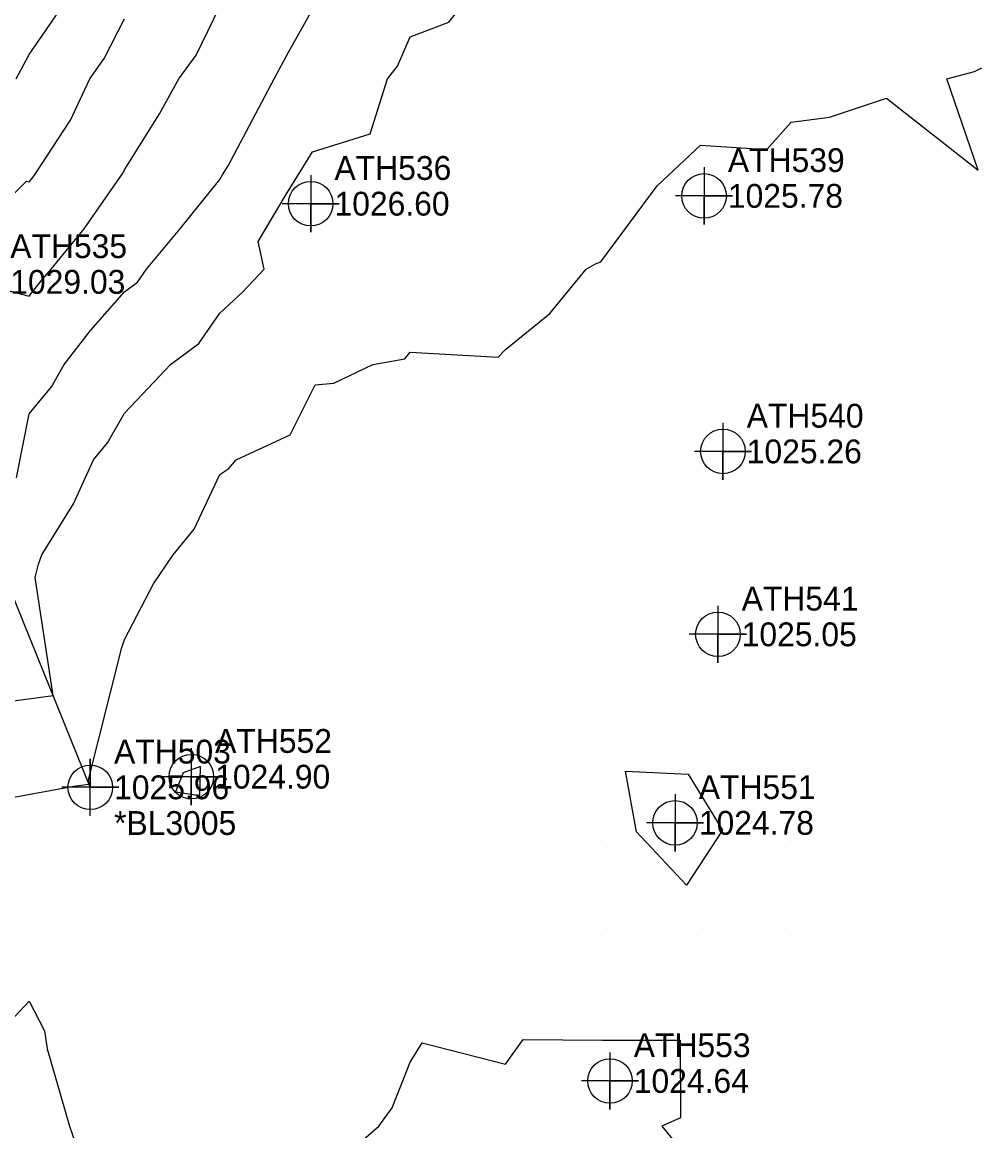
# Model space of a CAD drawing. Extents: x 1213164 to 1213550, y 766120 to 766870.
# Drawn here: x 1213419.3 to 1213520, y 766539.5 to 766656 of the extents above; entities that cross this region are included whole.
import ezdxf

# ---------------------------------------------------------------- set-up
doc = ezdxf.new("R2010")
doc.units = 0
for name, color, linetype in [('Default', 7, 'Continuous'), ('Exist DTM QL2 LIDAR Elevation Point', 7, 'Continuous'), ('Exist DTM Regular Point CELL', 7, 'Continuous'), ('Exist DTM Regular Point Cogo Elevation', 7, 'Continuous'), ('Exist DTM Regular Point Cogo Number', 7, 'Continuous'), ('Exist Roads Soil', 7, 'Continuous'), ('Exist Roads Soil Cogo Comment', 7, 'Continuous'), ('Exist Roads Soil Cogo Elevation', 7, 'Continuous'), ('Exist Roads Soil Cogo Number', 7, 'Continuous'), ('Exist Roads Soil Cogo Point CELL', 7, 'Continuous')]:
    doc.layers.add(name, color=color, linetype=linetype)

msp = doc.modelspace()

# ---------------------------------------------------------------- linework, layer by layer
at = {"layer": 'Default'}
for points in [[(1213403.52, 766582.69), (1213422.5, 766585.23), (1213420.62, 766597.62), (1213420.98, 766599.02), (1213421.33, 766600), (1213424.63, 766605.37), (1213426.75, 766610), (1213428.22, 766611.78), (1213430, 766614.9), (1213432.49, 766617.51), (1213434.81, 766620), (1213437.8, 766622.2), (1213440, 766625.38), (1213442.39, 766627.61), (1213444.66, 766630), (1213444.04, 766632.92), (1213446.89, 766637.76), (1213449.73, 766642.35), (1213455.77, 766644.23), (1213457.62, 766650), (1213458.66, 766651.34), (1213460, 766654.4), (1213464.06, 766655.94), (1213467.28, 766660)], [(1213415.71, 766628.28), (1213420, 766627.19), (1213421.23, 766628.77), (1213422.3, 766630), (1213425.75, 766634.25), (1213429.76, 766640), (1213429.86, 766640.14), (1213430, 766640.45), (1213433.66, 766646.34), (1213435.71, 766650), (1213437.52, 766652.48), (1213440, 766657.61)], [(1213418.63, 766650), (1213420, 766652.57), (1213423.02, 766656.98)], [(1213418.64, 766608.1), (1213420, 766614.82), (1213422.34, 766617.66), (1213423.67, 766620), (1213426.43, 766623.57), (1213430, 766627.64), (1213431.36, 766628.64), (1213432.3, 766630), (1213435.8, 766634.2), (1213440, 766639.44), (1213440.28, 766639.91), (1213440.87, 766640.87), (1213445.71, 766650), (1213447.2, 766652.8), (1213450, 766657.79)], [(1213353.03, 766538.71), (1213360.06, 766554.63), (1213361.94, 766557.96), (1213368.09, 766570.88), (1213369.21, 766573.11), (1213376.08, 766587.44), (1213384.56, 766603.77), (1213386.66, 766605.05), (1213387.56, 766605.71), (1213391.04, 766602.72), (1213405.84, 766608.43), (1213411.21, 766613.12), (1213411.8, 766620.77), (1213412.59, 766627.41), (1213412.01, 766629.52), (1213413.41, 766632.98), (1213419.7, 766639.25), (1213420, 766639.17), (1213420.37, 766639.63), (1213420.63, 766640), (1213424.33, 766645.67), (1213426.37, 766650), (1213427.85, 766652.15), (1213430, 766656.29)], [(1213406.87, 766572.47), (1213424.68, 766575.72), (1213426.26, 766575.93), (1213426.2, 766576.36), (1213429.71, 766590.29), (1213430, 766591.12), (1213433.03, 766596.97), (1213435.12, 766600), (1213437.31, 766602.69), (1213440, 766608.43), (1213440.94, 766609.06), (1213441.71, 766610), (1213447.4, 766612.6), (1213450, 766617.85), (1213451.97, 766618.03), (1213456.08, 766620), (1213459.42, 766620.58), (1213460, 766621.3), (1213469.24, 766620.76), (1213470, 766621.58), (1213474.66, 766625.34), (1213478.46, 766630), (1213479.44, 766630.56), (1213480, 766630.78), (1213485.92, 766638.75), (1213490.48, 766643.05), (1213497.43, 766642.57), (1213500, 766645.44), (1213504.02, 766645.98), (1213510, 766647.97), (1213519.6, 766640.4), (1213516.31, 766650), (1213519.24, 766650.76), (1213520, 766651.16)], [(1213437.98, 766577.78), (1213436.14, 766577.12), (1213435.34, 766575.12), (1213437.89, 766574.74), (1213437.98, 766577.78)], [(1213482.59, 766577.3), (1213489.18, 766576.97), (1213492.77, 766571.1), (1213489.01, 766565.31), (1213483.75, 766570.9), (1213482.59, 766577.3)], [(1213403.65, 766536.35), (1213401.85, 766540), (1213405.16, 766544.84), (1213405.95, 766550), (1213407.62, 766552.38), (1213410, 766555.03), (1213418.49, 766551.51), (1213420, 766553.14), (1213421.59, 766550), (1213421.87, 766548.13), (1213424.23, 766540), (1213426.51, 766533.49)], [(1213453.12, 766536.88), (1213456.69, 766540), (1213458.08, 766541.92), (1213460, 766546.73), (1213461.24, 766548.76), (1213470, 766546.5), (1213471.84, 766549.12), (1213480.17, 766549.05), (1213488.33, 766549.03), (1213488.36, 766540.86), (1213486.39, 766540), (1213490, 766535.63)]]:
    msp.add_lwpolyline(points, dxfattribs=at)
at = {"layer": 'Exist DTM QL2 LIDAR Elevation Point'}
for p, q in [((1213420, 766650), (1213420, 766650)), ((1213430, 766650), (1213430, 766650)), ((1213440, 766650), (1213440, 766650)), ((1213450, 766650), (1213450, 766650)), ((1213460, 766650), (1213460, 766650)), ((1213470, 766650), (1213470, 766650)), ((1213480, 766650), (1213480, 766650)), ((1213490, 766650), (1213490, 766650)), ((1213500, 766650), (1213500, 766650)), ((1213510, 766650), (1213510, 766650)), ((1213520, 766650), (1213520, 766650)), ((1213420, 766640), (1213420, 766640)), ((1213430, 766640), (1213430, 766640)), ((1213440, 766640), (1213440, 766640)), ((1213460, 766640), (1213460, 766640)), ((1213470, 766640), (1213470, 766640)), ((1213480, 766640), (1213480, 766640)), ((1213500, 766640), (1213500, 766640)), ((1213510, 766640), (1213510, 766640)), ((1213520, 766640), (1213520, 766640)), ((1213420, 766630), (1213420, 766630)), ((1213430, 766630), (1213430, 766630)), ((1213440, 766630), (1213440, 766630)), ((1213450, 766630), (1213450, 766630)), ((1213460, 766630), (1213460, 766630)), ((1213470, 766630), (1213470, 766630)), ((1213480, 766630), (1213480, 766630)), ((1213490, 766630), (1213490, 766630)), ((1213500, 766630), (1213500, 766630)), ((1213510, 766630), (1213510, 766630)), ((1213420, 766620), (1213420, 766620)), ((1213430, 766620), (1213430, 766620)), ((1213440, 766620), (1213440, 766620)), ((1213450, 766620), (1213450, 766620)), ((1213460, 766620), (1213460, 766620)), ((1213470, 766620), (1213470, 766620)), ((1213480, 766620), (1213480, 766620)), ((1213490, 766620), (1213490, 766620)), ((1213500, 766620), (1213500, 766620)), ((1213510, 766620), (1213510, 766620)), ((1213420, 766610), (1213420, 766610)), ((1213430, 766610), (1213430, 766610)), ((1213440, 766610), (1213440, 766610)), ((1213450, 766610), (1213450, 766610)), ((1213460, 766610), (1213460, 766610)), ((1213470, 766610), (1213470, 766610)), ((1213480, 766610), (1213480, 766610)), ((1213500, 766610), (1213500, 766610)), ((1213510, 766610), (1213510, 766610)), ((1213420, 766600), (1213420, 766600)), ((1213430, 766600), (1213430, 766600)), ((1213440, 766600), (1213440, 766600)), ((1213450, 766600), (1213450, 766600)), ((1213460, 766600), (1213460, 766600)), ((1213470, 766600), (1213470, 766600)), ((1213480, 766600), (1213480, 766600)), ((1213490, 766600), (1213490, 766600)), ((1213500, 766600), (1213500, 766600)), ((1213510, 766600), (1213510, 766600)), ((1213430, 766590), (1213430, 766590)), ((1213440, 766590), (1213440, 766590)), ((1213450, 766590), (1213450, 766590)), ((1213460, 766590), (1213460, 766590)), ((1213470, 766590), (1213470, 766590)), ((1213480, 766590), (1213480, 766590)), ((1213500, 766590), (1213500, 766590)), ((1213510, 766590), (1213510, 766590)), ((1213430, 766580), (1213430, 766580)), ((1213440, 766580), (1213440, 766580)), ((1213450, 766580), (1213450, 766580)), ((1213460, 766580), (1213460, 766580)), ((1213470, 766580), (1213470, 766580)), ((1213480, 766580), (1213480, 766580)), ((1213490, 766580), (1213490, 766580)), ((1213500, 766580), (1213500, 766580)), ((1213510, 766580), (1213510, 766580)), ((1213420, 766570), (1213420, 766570)), ((1213430, 766570), (1213430, 766570)), ((1213440, 766570), (1213440, 766570)), ((1213450, 766570), (1213450, 766570)), ((1213460, 766570), (1213460, 766570)), ((1213470, 766570), (1213470, 766570)), ((1213480, 766570), (1213480, 766570)), ((1213500, 766570), (1213500, 766570)), ((1213420, 766560), (1213420, 766560)), ((1213430, 766560), (1213430, 766560)), ((1213440, 766560), (1213440, 766560)), ((1213450, 766560), (1213450, 766560)), ((1213460, 766560), (1213460, 766560)), ((1213470, 766560), (1213470, 766560)), ((1213480, 766560), (1213480, 766560)), ((1213490, 766560), (1213490, 766560)), ((1213500, 766560), (1213500, 766560)), ((1213420, 766550), (1213420, 766550)), ((1213430, 766550), (1213430, 766550)), ((1213440, 766550), (1213440, 766550)), ((1213450, 766550), (1213450, 766550)), ((1213460, 766550), (1213460, 766550)), ((1213470, 766550), (1213470, 766550)), ((1213480, 766550), (1213480, 766550)), ((1213490, 766550), (1213490, 766550)), ((1213500, 766550), (1213500, 766550)), ((1213420, 766540), (1213420, 766540)), ((1213430, 766540), (1213430, 766540)), ((1213440, 766540), (1213440, 766540)), ((1213450, 766540), (1213450, 766540)), ((1213460, 766540), (1213460, 766540)), ((1213470, 766540), (1213470, 766540)), ((1213480, 766540), (1213480, 766540)), ((1213490, 766540), (1213490, 766540)), ((1213500, 766540), (1213500, 766540))]:
    msp.add_line(p, q, dxfattribs=at)
at = {"layer": 'Exist DTM Regular Point CELL'}
for points in [[(1213490.84, 766640.71), (1213490.84, 766634.71), (1213490.84, 766637.71), (1213493.84, 766637.71), (1213487.84, 766637.71)], [(1213449.54, 766639.89), (1213449.54, 766633.89), (1213449.54, 766636.89), (1213452.54, 766636.89), (1213446.54, 766636.89)], [(1213492.82, 766613.87), (1213492.82, 766607.87), (1213492.82, 766610.87), (1213495.82, 766610.87), (1213489.82, 766610.87)], [(1213492.29, 766594.66), (1213492.29, 766588.66), (1213492.29, 766591.66), (1213495.29, 766591.66), (1213489.29, 766591.66)], [(1213437.01, 766579.71), (1213437.01, 766573.71), (1213437.01, 766576.71), (1213440.01, 766576.71), (1213434.01, 766576.71)], [(1213487.79, 766574.86), (1213487.79, 766568.86), (1213487.79, 766571.86), (1213490.79, 766571.86), (1213484.79, 766571.86)], [(1213480.96, 766547.75), (1213480.96, 766541.75), (1213480.96, 766544.75), (1213483.96, 766544.75), (1213477.96, 766544.75)]]:
    msp.add_lwpolyline(points, dxfattribs=at)
for centre in [(1213449.54, 766636.89), (1213490.84, 766637.71), (1213492.82, 766610.87), (1213492.29, 766591.66), (1213437.01, 766576.71), (1213487.79, 766571.86), (1213480.96, 766544.75)]:
    msp.add_circle(centre, 2.34, dxfattribs=at)
at = {"layer": 'Exist Roads Soil'}
msp.add_line((1213426.4, 766575.59), (1213398.12, 766645.45), dxfattribs=at)
at = {"layer": 'Exist Roads Soil Cogo Point CELL'}
msp.add_lwpolyline([(1213426.4, 766572.59), (1213426.4, 766578.59), (1213426.4, 766575.59), (1213429.4, 766575.59), (1213423.4, 766575.59)], dxfattribs=at)
msp.add_circle((1213426.4, 766575.59), 2.34, dxfattribs=at)

# ---------------------------------------------------------------- texts
at = {"layer": 'Exist DTM Regular Point Cogo Elevation'}
for s, p in [('1026.60', (1213452.04, 766635.64)), ('1025.78', (1213493.34, 766636.46)), ('1029.03', (1213418, 766627.43)), ('1025.26', (1213495.32, 766609.62)), ('1025.05', (1213494.79, 766590.41)), ('1024.90', (1213439.51, 766575.46)), ('1024.78', (1213490.29, 766570.61)), ('1024.64', (1213483.46, 766543.5))]:
    msp.add_text(s, height=2.5, dxfattribs=at).set_placement(p)
at = {"layer": 'Exist DTM Regular Point Cogo Number'}
for s, p in [('ATH539', (1213493.34, 766640.21)), ('ATH536', (1213452.04, 766639.39)), ('ATH535', (1213418, 766631.18)), ('ATH540', (1213495.32, 766613.37)), ('ATH541', (1213494.79, 766594.16)), ('ATH552', (1213439.51, 766579.21)), ('ATH551', (1213490.29, 766574.36)), ('ATH553', (1213483.46, 766547.25))]:
    msp.add_text(s, height=2.5, dxfattribs=at).set_placement(p)
at = {"layer": 'Exist Roads Soil Cogo Comment'}
msp.add_text('*BL3005', height=2.5, dxfattribs=at).set_placement((1213428.9, 766570.59))
at = {"layer": 'Exist Roads Soil Cogo Elevation'}
msp.add_text('1025.96', height=2.5, dxfattribs=at).set_placement((1213428.9, 766574.34))
at = {"layer": 'Exist Roads Soil Cogo Number'}
msp.add_text('ATH503', height=2.5, dxfattribs=at).set_placement((1213428.9, 766578.09))

doc.saveas('drawing.dxf')
